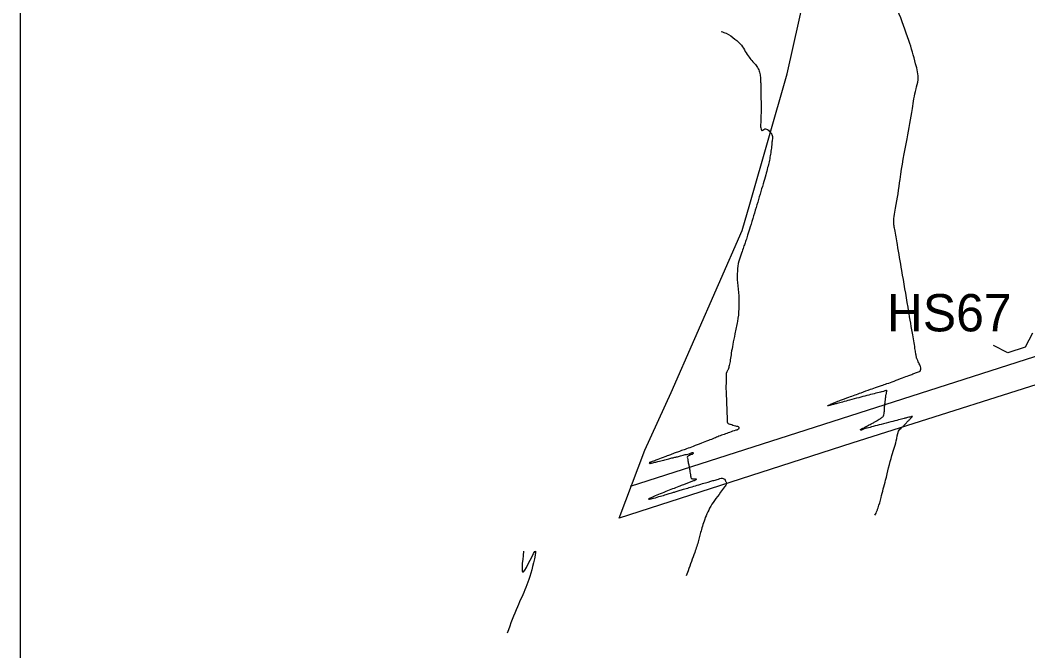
# Model space of a CAD drawing. Extents: x -478232 to -472707, y -1118753 to -1113967.
# Drawn here: x -478232.1 to -477962.2, y -1117555.4 to -1117386.4 of the extents above; entities that cross this region are included whole.
import ezdxf

# ---------------------------------------------------------------- set-up
doc = ezdxf.new("R2010")
doc.units = 0
for name, color, linetype in [('hospodářské sjezdy', 7, 'Continuous'), ('ObPÚ', 7, 'Continuous'), ('ramecek', 7, 'Continuous'), ('silnice', 7, 'Continuous'), ('Vrstevnice_vedlejsi', 7, 'Continuous')]:
    doc.layers.add(name, color=color, linetype=linetype)

msp = doc.modelspace()

# ---------------------------------------------------------------- linework, layer by layer
at = {"layer": 'hospodářské sjezdy'}
for p, q in [((-477960.951, -1117470.316), (-477962.923, -1117474.099)), ((-477967.582, -1117475.568), (-477971.367, -1117473.601)), ((-477962.923, -1117474.099), (-477967.582, -1117475.568))]:
    msp.add_line(p, q, dxfattribs=at)
at = {"layer": 'ObPÚ'}
msp.add_lwpolyline([(-477945.12, -1117479.46), (-478009.37, -1117499.81), (-478071.71, -1117519.91), (-478064.79, -1117501.64), (-478057.71, -1117486.26), (-478038.68, -1117442.8), (-478036.665, -1117435.774), (-478026.64, -1117400.81), (-478007.71, -1117316.06), (-478010.688, -1117315.457), (-478014.916, -1117299.841), (-478003.02, -1117297.83), (-477955.02, -1117226.727)], dxfattribs=at)
at = {"layer": 'ramecek'}
msp.add_lwpolyline([(-478232.145, -1118752.755), (-472706.727, -1118752.755), (-472706.727, -1113967.019), (-478232.145, -1113967.019)], close=True, dxfattribs=at)
at = {"layer": 'silnice'}
msp.add_lwpolyline([(-478068.596, -1117511.329), (-477917.95, -1117462.993), (-477779.219, -1117418.245), (-477732.944, -1117407.585), (-477720.808, -1117405.048), (-477704.588, -1117403.835), (-477689.402, -1117401.926), (-477652.852, -1117401.691), (-477590.784, -1117403.37), (-477332.447, -1117414.279), (-477204.956, -1117416.797), (-477142.049, -1117416.797), (-477096.756, -1117410.083), (-477036.34, -1117397.174), (-476978.492, -1117379.033), (-476883.712, -1117344.626), (-476756.221, -1117298.47), (-476633.763, -1117254.832), (-476588.47, -1117242.245), (-476550.726, -1117234.692), (-476503.755, -1117230.496), (-476424.073, -1117228.817), (-476282.324, -1117220.425)], dxfattribs=at)
at = {"layer": 'Vrstevnice_vedlejsi'}
msp.add_line((-478053.213, -1117534.03), (-478053.687, -1117535.309), dxfattribs=at)
for points in [[(-477998.879, -1117255.557), (-477998.727, -1117255.77), (-477994.613, -1117261.766), (-477989.226, -1117270.883), (-477986.788, -1117279.171), (-477987.299, -1117286.631), (-477990.759, -1117293.261), (-477991.682, -1117299.15), (-477990.068, -1117304.296), (-477985.915, -1117308.701), (-477982.328, -1117312.403), (-477979.306, -1117315.404), (-477976.849, -1117317.702), (-477973.612, -1117321.957), (-477969.594, -1117328.168), (-477964.797, -1117336.336), (-477960.899, -1117343.504), (-477957.9, -1117349.67), (-477955.8, -1117354.835), (-477954.323, -1117359.055), (-477953.469, -1117362.331), (-477953.239, -1117364.661), (-477952.282, -1117369.883), (-477950.598, -1117377.995), (-477948.188, -1117388.997), (-477946.693, -1117397.801), (-477946.113, -1117404.405), (-477946.449, -1117408.81), (-477947.352, -1117414.723), (-477948.823, -1117422.144), (-477950.861, -1117431.072), (-477952.177, -1117437.645), (-477952.771, -1117441.863), (-477952.644, -1117443.726), (-477952.589, -1117445.223), (-477952.606, -1117446.354), (-477952.696, -1117447.119), (-477952.711, -1117448.007), (-477952.649, -1117449.018), (-477952.512, -1117450.153), (-477952.156, -1117452.114), (-477951.583, -1117454.901), (-477950.791, -1117458.515), (-477949.91, -1117461.246), (-477948.939, -1117463.094), (-477947.878, -1117464.059), (-477947.136, -1117464.728), (-477946.712, -1117465.101), (-477946.606, -1117465.179), (-477946.495, -1117465.26), (-477946.379, -1117465.346), (-477946.257, -1117465.436), (-477946.233, -1117465.524), (-477946.307, -1117465.609), (-477946.478, -1117465.691), (-477946.651, -1117465.772), (-477946.824, -1117465.851), (-477946.999, -1117465.928), (-477947.792, -1117466.25), (-477949.203, -1117466.816), (-477951.232, -1117467.627), (-477953.439, -1117468.556), (-477955.824, -1117469.604), (-477958.387, -1117470.771), (-477959.194, -1117471.349), (-477958.243, -1117471.339)], [(-477991.867, -1117477.245), (-477991.928, -1117477.172), (-477992.04, -1117476.677), (-477992.202, -1117475.763), (-477992.413, -1117474.428), (-477993.107, -1117470.277), (-477994.282, -1117463.311), (-477995.94, -1117453.528), (-477997.123, -1117446.591), (-477997.83, -1117442.497), (-477998.062, -1117441.249), (-477997.593, -1117436.785), (-477996.423, -1117429.106), (-477994.553, -1117418.212), (-477993.126, -1117410.136), (-477992.143, -1117404.879), (-477991.604, -1117402.439), (-477992.237, -1117398.118), (-477994.043, -1117391.915), (-477997.021, -1117383.831), (-477999.558, -1117377.283), (-478001.654, -1117372.273), (-478003.307, -1117368.799), (-478004.636, -1117365.887), (-478005.64, -1117363.535), (-478006.319, -1117361.745), (-478007.439, -1117358.786), (-478009, -1117354.657), (-478011.003, -1117349.359), (-478012.316, -1117345.574), (-478012.939, -1117343.304), (-478012.872, -1117342.547), (-478012.777, -1117341.561), (-478012.655, -1117340.344), (-478012.505, -1117338.897), (-478012.348, -1117337.07), (-478012.182, -1117334.863), (-478012.009, -1117332.276), (-478011.775, -1117329.718), (-478011.478, -1117327.189), (-478011.12, -1117324.688), (-478010.876, -1117322.931), (-478010.745, -1117321.917), (-478010.728, -1117321.646), (-478010.753, -1117321.243), (-478010.821, -1117320.708), (-478010.93, -1117320.041), (-478011.029, -1117319.606), (-478011.115, -1117319.402), (-478011.19, -1117319.431), (-478011.241, -1117319.41), (-478011.268, -1117319.341), (-478011.271, -1117319.224), (-478011.447, -1117318.941), (-478011.795, -1117318.493), (-478012.316, -1117317.879), (-478012.672, -1117317.097), (-478012.863, -1117316.147), (-478012.89, -1117315.028), (-478012.892, -1117314.215), (-478012.869, -1117313.71), (-478012.821, -1117313.512), (-478012.909, -1117313.243), (-478013.131, -1117312.902), (-478013.489, -1117312.491), (-478013.809, -1117312.342), (-478014.093, -1117312.455), (-478014.34, -1117312.83), (-478014.581, -1117313.247), (-478014.817, -1117313.705), (-478015.046, -1117314.206), (-478015.238, -1117314.822), (-478015.392, -1117315.554), (-478015.508, -1117316.401), (-478015.602, -1117317.301), (-478015.672, -1117318.253), (-478015.72, -1117319.257), (-478015.808, -1117320.173), (-478015.935, -1117321.003), (-478016.103, -1117321.746), (-478016.33, -1117322.362), (-478016.618, -1117322.853), (-478016.967, -1117323.218), (-478017.343, -1117323.742), (-478017.748, -1117324.426), (-478018.182, -1117325.269), (-478018.755, -1117325.029), (-478019.468, -1117323.706), (-478020.32, -1117321.3), (-478021.282, -1117318.195), (-478022.355, -1117314.389), (-478023.538, -1117309.884), (-478024.297, -1117305.737), (-478024.625, -1117302.334)], [(-478044.323, -1117389.497), (-478042.996, -1117389.964), (-478040.645, -1117391.528), (-478038.938, -1117393.157), (-478037.876, -1117394.852), (-478036.855, -1117396.325), (-478035.874, -1117397.575), (-478034.935, -1117398.602), (-478034.275, -1117399.76), (-478033.895, -1117401.05), (-478033.795, -1117402.47), (-478033.734, -1117403.559), (-478033.712, -1117404.316), (-478033.729, -1117404.741), (-478033.725, -1117405.596), (-478033.699, -1117406.882), (-478033.652, -1117408.598), (-478033.647, -1117410.423), (-478033.685, -1117412.357), (-478033.765, -1117414.398), (-478033.662, -1117415.636), (-478033.377, -1117416.07), (-478032.909, -1117415.7), (-478032.433, -1117415.597), (-478031.948, -1117415.763), (-478031.455, -1117416.196), (-478031.095, -1117416.556), (-478030.869, -1117416.842), (-478030.778, -1117417.054), (-478030.702, -1117417.25), (-478030.642, -1117417.43), (-478030.599, -1117417.594), (-478030.633, -1117418.265), (-478030.746, -1117419.442), (-478030.936, -1117421.127), (-478031.189, -1117422.771), (-478031.506, -1117424.376), (-478031.885, -1117425.94), (-478032.413, -1117427.911), (-478033.089, -1117430.288), (-478033.913, -1117433.072), (-478034.768, -1117435.929), (-478035.655, -1117438.861), (-478036.572, -1117441.865), (-478037.258, -1117444.074), (-478037.711, -1117445.486), (-478037.933, -1117446.102), (-478038.323, -1117447.233), (-478038.882, -1117448.881), (-478039.609, -1117451.044), (-478039.974, -1117453.668), (-478039.978, -1117456.752), (-478039.62, -1117460.297), (-478039.614, -1117463.766), (-478039.96, -1117467.16), (-478040.659, -1117470.478), (-478041.215, -1117473.309), (-478041.627, -1117475.65), (-478041.895, -1117477.504), (-478042.188, -1117478.963), (-478042.508, -1117480.028), (-478042.852, -1117480.698), (-478043.034, -1117482.402), (-478043.052, -1117485.14), (-478042.907, -1117488.911), (-478042.811, -1117491.623), (-478042.763, -1117493.276), (-478042.764, -1117493.87), (-478042.605, -1117494.312), (-478042.286, -1117494.604), (-478041.807, -1117494.745), (-478041.205, -1117494.94), (-478040.478, -1117495.19), (-478039.628, -1117495.494), (-478039.61, -1117495.88), (-478040.424, -1117496.348), (-478042.07, -1117496.896), (-478043.579, -1117497.431), (-478044.951, -1117497.952), (-478046.187, -1117498.458), (-478047.753, -1117499.08), (-478049.649, -1117499.817), (-478051.876, -1117500.669), (-478053.635, -1117501.33), (-478054.925, -1117501.799), (-478055.746, -1117502.077), (-478056.417, -1117502.312), (-478056.936, -1117502.505), (-478057.304, -1117502.655), (-478058.15, -1117502.98), (-478059.473, -1117503.48)], [(-478003.144, -1117519.112), (-478003.132, -1117519.091), (-478002.849, -1117518.531), (-478002.564, -1117517.866), (-478002.277, -1117517.095), (-478001.519, -1117514.373), (-478000.289, -1117509.7), (-477998.587, -1117503.075), (-477997.307, -1117498.528), (-477996.448, -1117496.058), (-477996.011, -1117495.664), (-477995.494, -1117495.164), (-477994.897, -1117494.557), (-477994.22, -1117493.842), (-477993.709, -1117493.305), (-477993.364, -1117492.946), (-477993.185, -1117492.764), (-477993.124, -1117492.659), (-477993.181, -1117492.63), (-477993.356, -1117492.676), (-477993.771, -1117492.785), (-477994.426, -1117492.954), (-477995.322, -1117493.185), (-477996.795, -1117493.562), (-477998.846, -1117494.085), (-478001.473, -1117494.753), (-478003.611, -1117495.312), (-478005.26, -1117495.76), (-478006.419, -1117496.098), (-478006.996, -1117496.219), (-478006.993, -1117496.123), (-478006.408, -1117495.809), (-478005.709, -1117495.438), (-478004.894, -1117495.01), (-478003.965, -1117494.524), (-478003.169, -1117494.089), (-478002.505, -1117493.706), (-478001.974, -1117493.373), (-478001.536, -1117493.087), (-478001.191, -1117492.847), (-478000.937, -1117492.652), (-478000.751, -1117492.194), (-478000.632, -1117491.473), (-478000.581, -1117490.488), (-478000.498, -1117489.492), (-478000.385, -1117488.485), (-478000.24, -1117487.467), (-478000.128, -1117486.703), (-478000.048, -1117486.194), (-478000.001, -1117485.94), (-477999.965, -1117485.766), (-477999.941, -1117485.673), (-477999.928, -1117485.661), (-478000.489, -1117485.799), (-478001.623, -1117486.089), (-478003.33, -1117486.529), (-478005.282, -1117487.037), (-478007.479, -1117487.611), (-478009.922, -1117488.252), (-478011.864, -1117488.767), (-478013.305, -1117489.157), (-478014.246, -1117489.421), (-478014.977, -1117489.616), (-478015.498, -1117489.744), (-478015.809, -1117489.803), (-478015.836, -1117489.758), (-478015.578, -1117489.608), (-478015.036, -1117489.355), (-478014.549, -1117489.136), (-478014.118, -1117488.952), (-478013.741, -1117488.803), (-478012.405, -1117488.306), (-478010.108, -1117487.462), (-478006.85, -1117486.27), (-478004.315, -1117485.357), (-478002.502, -1117484.722), (-478001.412, -1117484.367), (-477999.922, -1117483.843), (-477998.032, -1117483.15), (-477995.742, -1117482.288), (-477994.054, -1117481.654), (-477992.967, -1117481.248), (-477992.483, -1117481.068), (-477991.998, -1117480.879), (-477991.512, -1117480.68), (-477991.026, -1117480.472), (-477990.843, -1117480.006), (-477990.962, -1117479.282), (-477991.383, -1117478.3), (-477991.685, -1117477.622), (-477991.867, -1117477.245)], [(-478059.473, -1117503.48), (-478061.273, -1117504.155), (-478062.505, -1117504.62), (-478063.169, -1117504.874), (-478063.265, -1117504.919), (-478063.348, -1117504.951), (-478063.419, -1117504.972), (-478063.477, -1117504.981), (-478063.524, -1117504.995), (-478063.56, -1117505.013), (-478063.585, -1117505.036), (-478063.595, -1117505.066), (-478063.591, -1117505.103), (-478063.57, -1117505.147), (-478063.526, -1117505.177), (-478063.458, -1117505.194), (-478063.366, -1117505.198), (-478063.254, -1117505.189), (-478063.124, -1117505.167), (-478062.974, -1117505.132), (-478062.359, -1117504.978), (-478061.278, -1117504.705), (-478059.732, -1117504.311), (-478058.385, -1117503.975), (-478057.239, -1117503.697), (-478056.293, -1117503.477), (-478055.194, -1117503.201), (-478053.942, -1117502.871), (-478052.538, -1117502.485), (-478051.841, -1117502.369), (-478051.851, -1117502.521), (-478052.569, -1117502.943), (-478053.063, -1117503.23), (-478053.334, -1117503.384), (-478053.381, -1117503.404), (-478053.347, -1117503.774), (-478053.23, -1117504.495), (-478053.03, -1117505.565), (-478052.853, -1117506.552), (-478052.698, -1117507.454), (-478052.564, -1117508.272), (-478052.466, -1117508.842), (-478052.403, -1117509.165), (-478052.374, -1117509.239), (-478052.188, -1117509.294), (-478051.845, -1117509.328), (-478051.344, -1117509.342), (-478051.064, -1117509.394), (-478051.005, -1117509.486), (-478051.168, -1117509.616), (-478051.427, -1117509.761), (-478051.782, -1117509.921), (-478052.234, -1117510.097), (-478052.683, -1117510.269), (-478053.128, -1117510.439), (-478053.57, -1117510.606), (-478054.428, -1117510.934), (-478055.701, -1117511.423), (-478057.392, -1117512.072), (-478059.194, -1117512.787), (-478061.11, -1117513.568), (-478063.138, -1117514.415), (-478063.798, -1117514.79), (-478063.089, -1117514.692), (-478061.01, -1117514.123), (-478059.39, -1117513.667), (-478058.228, -1117513.324), (-478057.524, -1117513.095), (-478056.651, -1117512.821), (-478055.61, -1117512.502), (-478054.401, -1117512.139), (-478052.948, -1117511.707), (-478051.253, -1117511.208), (-478049.313, -1117510.64), (-478047.84, -1117510.209), (-478046.831, -1117509.914), (-478046.288, -1117509.755), (-478045.694, -1117509.584), (-478045.048, -1117509.401), (-478044.351, -1117509.205), (-478043.802, -1117509.228), (-478043.401, -1117509.471), (-478043.149, -1117509.932), (-478042.982, -1117510.283), (-478042.902, -1117510.524), (-478042.908, -1117510.653), (-478043.448, -1117511.466), (-478044.521, -1117512.962), (-478046.128, -1117515.142), (-478047.422, -1117517.235), (-478048.402, -1117519.244), (-478049.068, -1117521.166), (-478049.621, -1117522.911), (-478050.059, -1117524.479), (-478050.382, -1117525.869), (-478051.434, -1117529.052), (-478053.213, -1117534.03)], [(-478097.26, -1117528.759), (-478097.327, -1117534.259), (-478094.062, -1117528.696), (-478094.59, -1117531.824), (-478098.909, -1117543.642), (-478101.702, -1117550.697)]]:
    msp.add_spline(points, degree=3, dxfattribs=at)

# ---------------------------------------------------------------- texts
at = {"layer": 'hospodářské sjezdy'}
msp.add_text('HS67', height=10, rotation=359.99999, dxfattribs=at).set_placement((-477999.969, -1117469.838))

doc.saveas('drawing.dxf')
